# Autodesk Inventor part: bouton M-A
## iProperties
Created: 2010-07
Part Number: bouton M-A
Document SubType Name: Modeling
Designer: eric
Density: 1 g/cm^3
Mass: 0.0526831 g
Surface Area: 1.361 cm^2
Volume: 0.0526831 cm^3
Author: eric
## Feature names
1. Extrusion4
2. Extrusion3
3. Fillet1
4. Extrusion2
5. Extrusion1
